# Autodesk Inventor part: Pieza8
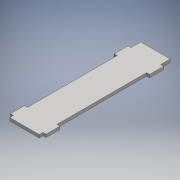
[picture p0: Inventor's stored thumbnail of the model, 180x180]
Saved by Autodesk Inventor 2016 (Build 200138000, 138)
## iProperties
Created: 2016-06
Part Number: Pieza8
Material: Genérico
Document SubType Name: Modeling
Designer: adm
Density: 1 g/cm^3
Appearance: Valor por defecto
Author: adm
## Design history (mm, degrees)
sketch "Boceto1"
  geometry: L1 (29.5, -125)-(-29.5, -125); L2 (-29.5, 125)-(29.5, 125); L3 (29.5, -125)-(-29.5, 125); L4 (-29.5, -125)-(29.5, 125); L5 (29.5, 117.561)-(35.5, 117.561); L6 (35.5, 117.561)-(35.5, 89.561); L7 (35.5, 89.561)-(29.5, 89.561); L8 (0, 0)-(-55.304, 0); L9 (0, 0)-(0, -42.823); L10 (-29.5, 117.561)-(-35.5, 117.561); L11 (-35.5, 117.561)-(-35.5, 89.561); L12 (-35.5, 89.561)-(-29.5, 89.561); L13 (35.5, -89.56)-(29.5, -89.56); L14 (35.5, -117.56)-(35.5, -89.56); L15 (29.5, -117.56)-(35.5, -117.56); L16 (-35.5, -89.561)-(-29.5, -89.561); L17 (-29.5, -117.561)-(-35.5, -117.561); L18 (-35.5, -117.561)-(-35.5, -89.561); L19 (29.5, -117.56)-(29.5, -125); L20 (-29.5, -125)-(-29.5, -117.561); L21 (-29.5, -89.561)-(-29.5, 89.561); L22 (-29.5, 117.561)-(-29.5, 125); L23 (29.5, 125)-(29.5, 117.561); L24 (29.5, 89.561)-(29.5, -89.56)
  constraints: 48 end point, 12 symmetric about line, 11 parallel, 4 perpendicular, 3 horizontal, 2 midpoint, 1 vertical
  dimensions: "d0" = 59 distance of L1.start L1.end; "d1" = 250 distance of L2.end L1.start; "d2" = 28 distance of L5.end L6.end; "d3" = 6 distance of L6.end L7.end; "d4" = 117.5605 distance from line of L5 L8.start
extrude "Extrusión1" new body sketch "Boceto1" distance "d5" = 6; taper "d6" = 0 deg
sketch "Boceto2"
  geometry: L1 (29.5, 125)-(-29.5, 125) reference; L2 (-29.5, 125)-(29.5, 125); L3 (29.5, 125)-(29.5, 137); L4 (29.5, 137)-(-29.5, 137); L5 (-29.5, 137)-(-29.5, 125); 1 further point
  constraints: 8 end point, 2 parallel, 1 horizontal, 1 perpendicular
  dimensions: "d7" = 12 distance of L3.end L2.end
extrude "Extrusión2" join sketch "Boceto2" distance "d8" = 6; taper "d9" = 0 deg
node "Sólido1"
